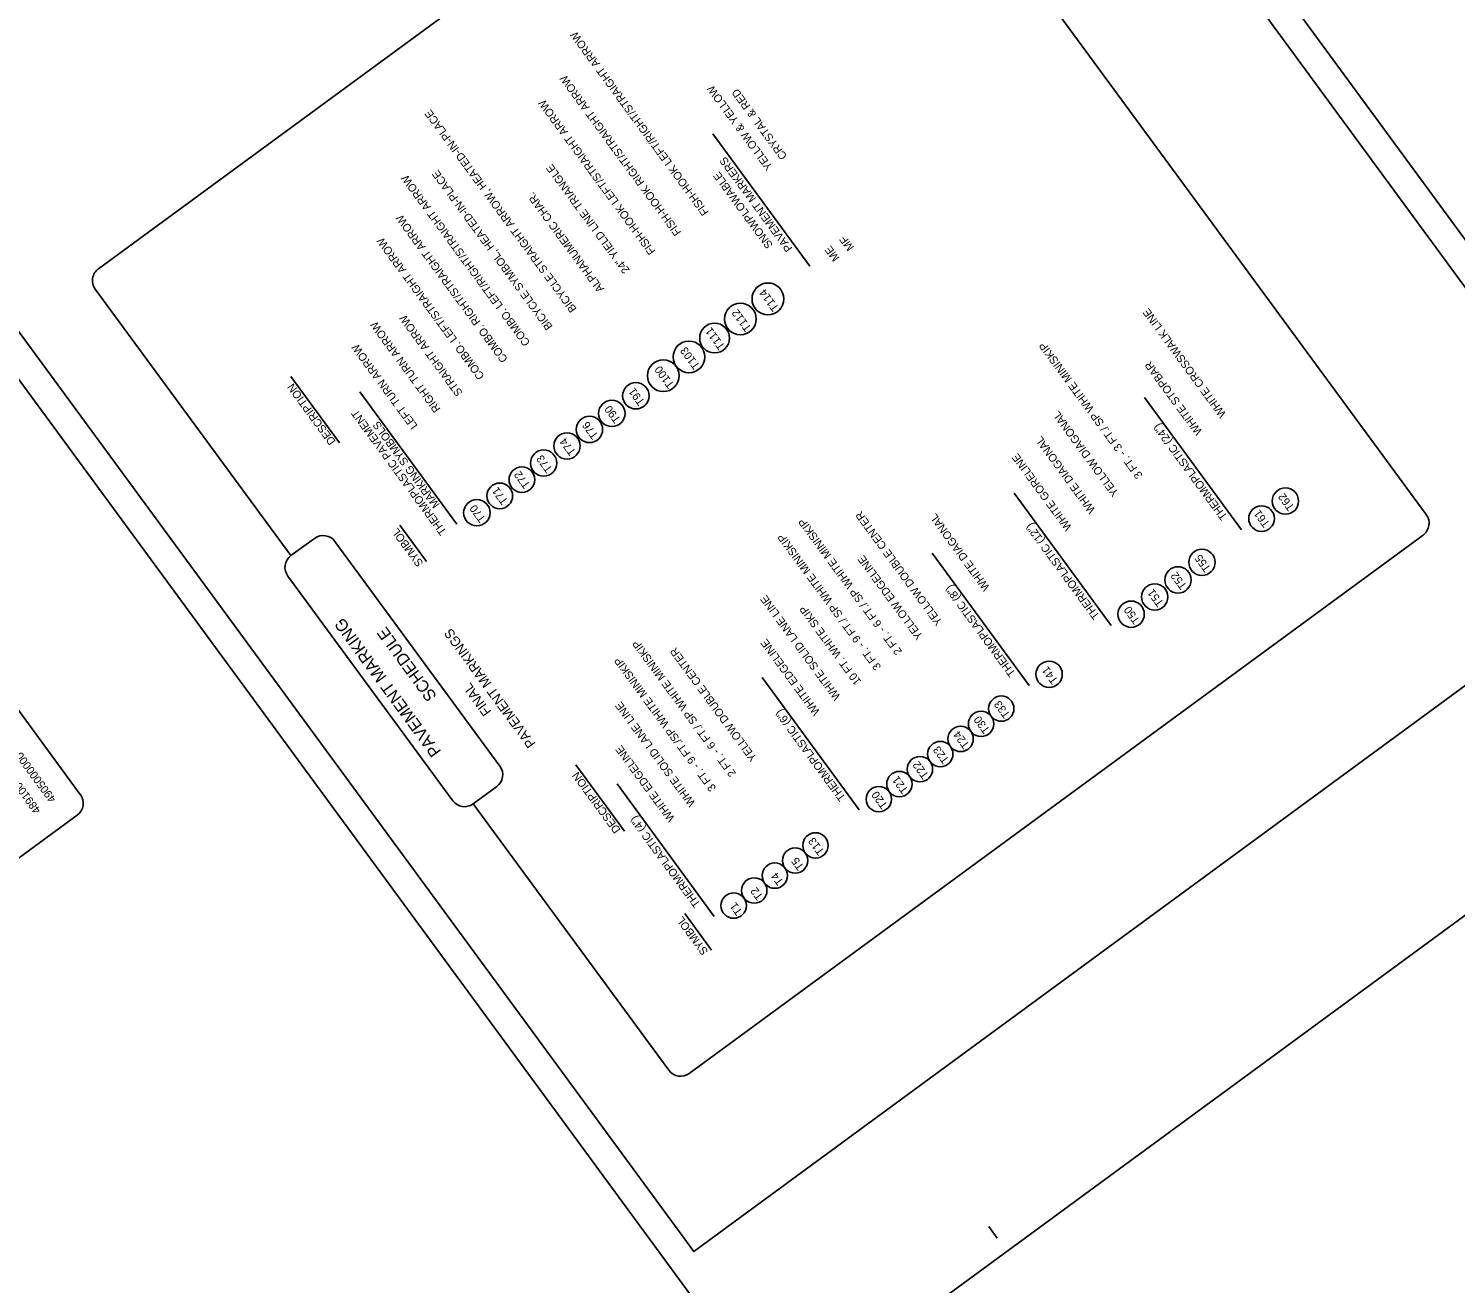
# Model space of a CAD drawing. Extents: x 719153 to 721402, y 581205 to 583188.
# Drawn here: x 720080 to 720834, y 581830 to 582493 of the extents above; entities that cross this region are included whole.
import ezdxf

# ---------------------------------------------------------------- set-up
doc = ezdxf.new("R2010")
doc.units = 0
for name, color, linetype in [('Default', 7, 'Continuous'), ('Old_Level_1', 7, 'Continuous'), ('Old_Level_50', 7, 'Continuous'), ('Sheet Plot Border Inside CELL', 7, 'Continuous'), ('Sheet Sticker Incomplete CELL', 7, 'Continuous')]:
    doc.layers.add(name, color=color, linetype=linetype)

msp = doc.modelspace()

# ---------------------------------------------------------------- linework, layer by layer
at = {"layer": 'Default'}
for p, q in [((719824.66, 582472.96), (720107.28, 582088.04)), ((720037.42, 582027.11), (720105.64, 582077.23))]:
    msp.add_line(p, q, dxfattribs=at)
msp.add_arc((720101.06, 582083.45), 7.73, 306.36664, 36.36664, dxfattribs=at)
at = {"layer": 'Old_Level_1'}
for centre, radius in [((720470.61, 582349.98), 8.4), ((720456.09, 582339.33), 8.37), ((720442.44, 582329.3), 7.88), ((720428.88, 582319.35), 8.37), ((720415.31, 582309.39), 8.39), ((720400.83, 582298.78), 6.97), ((720388.13, 582289.47), 6.97), ((720376.32, 582280.98), 6.96), ((720364.45, 582272.27), 6.96), ((720352.12, 582263.22), 6.96), ((720340.6, 582254.45), 6.78), ((720328.93, 582245.89), 6.78), ((720744.08, 582243.14), 6.96), ((720316.81, 582236.99), 6.97), ((720731.47, 582233.89), 6.78), ((720699.96, 582210.77), 6.96), ((720687.31, 582201.49), 6.96), ((720675.02, 582192.47), 6.96), ((720662.55, 582183.36), 6.96), ((720619.23, 582151.59), 6.96), ((720593.95, 582133.45), 6.7), ((720583.25, 582125.38), 6.7), ((720572.46, 582117.44), 6.7), ((720561.71, 582109.45), 6.7), ((720550.95, 582101.47), 6.7), ((720540.1, 582093.61), 6.7), ((720529.23, 582085.63), 6.7), ((720495.75, 582061.17), 6.7), ((720485, 582053.18), 6.7), ((720474.25, 582045.19), 6.7), ((720463.4, 582037.34), 6.7), ((720452.52, 582029.36), 6.7)]:
    msp.add_circle(centre, radius, dxfattribs=at)
at = {"layer": 'Old_Level_50'}
msp.add_lwpolyline([(721009.35, 582149.27), (720410.24, 582965.86), (719878.1, 582575.44), (720477.21, 581758.85)], close=True, dxfattribs=at)
at = {"layer": 'Sheet Plot Border Inside CELL'}
for p, q in [((720591.8, 581853.7), (720587.36, 581859.75)), ((720431.1, 581847.05), (720431.1, 581847.05))]:
    msp.add_line(p, q, dxfattribs=at)
msp.add_lwpolyline([(719899.07, 582572.22), (720431.46, 581846.57), (720939.41, 582219.25), (720407.02, 582944.89)], close=True, dxfattribs=at)
at = {"layer": 'Sheet Sticker Incomplete CELL'}
for p, q in [((720116.85, 582365.91), (720504.77, 582650.51)), ((720818.48, 582236), (720515.57, 582648.85)), ((720492.79, 582367.32), (720441.52, 582437.29)), ((720218.57, 582214.29), (720115.19, 582355.1)), ((720244.29, 582273.93), (720218.6, 582309)), ((720306.31, 582230.96), (720255.05, 582300.93)), ((720720.95, 582227.89), (720669.69, 582297.86)), ((720651.99, 582177.42), (720600.72, 582247.39)), ((720290.26, 582211.13), (720276.08, 582230.49)), ((720816.84, 582225.16), (720526.73, 582012.31)), ((720218.57, 582214.29), (720231.04, 582223.44)), ((720241.85, 582221.78), (720328.99, 582103.08)), ((720608.67, 582145.64), (720557.41, 582215.61)), ((720216.91, 582203.49), (720304.06, 582084.78)), ((720518.83, 582079.96), (720467.57, 582149.93)), ((720394.85, 582068.69), (720369.17, 582103.75)), ((720314.87, 582083.12), (720327.33, 582092.27)), ((720442.13, 582023.68), (720390.87, 582093.65)), ((720418.26, 581942.31), (720314.87, 582083.13)), ((720440.82, 582005.89), (720426.64, 582025.24)), ((720429.07, 581940.65), (720526.73, 582012.31))]:
    msp.add_line(p, q, dxfattribs=at)
for centre, start, end in [((720121.42, 582359.67), 126.26669, 216.26669), ((720812.27, 582231.39), 306.26669, 36.26669), ((720235.62, 582217.21), 36.26669, 126.26669), ((720223.15, 582208.06), 126.26669, 216.26669), ((720322.76, 582098.5), 306.26664, 36.26664), ((720310.29, 582089.36), 216.26664, 306.26664), ((720424.49, 581946.89), 216.26664, 306.26664)]:
    msp.add_arc(centre, 7.73, start, end, dxfattribs=at)

# ---------------------------------------------------------------- texts
at = {"layer": 'Old_Level_1'}
for s, height, rotation, p in [('FISH-HOOK LEFT/RIGHT/STRAIGHT ARROW', 4.21, 126.22647, (720439.55, 582395.87)), ('FISH-HOOK RIGHT/STRAIGHT ARROW', 4.21, 126.22647, (720424.98, 582385.18)), ('YELLOW & YELLOW', 4.21, 126.22647, (720473.34, 582419.85)), ('CRYSTAL & RED', 4.21, 126.22647, (720480.97, 582425.45)), ('FISH-HOOK LEFT/STRAIGHT ARROW', 4.21, 126.22647, (720411.4, 582375.22)), ('BICYCLE STRAIGHT ARROW, HEATED-IN-PLACE', 4.21, 126.22647, (720369.75, 582344.72)), ('24" YIELD LINE TRIANGLE', 4.21, 126.22647, (720397.82, 582365.27)), ('PAVEMENT MARKERS', 4.21, 126.22647, (720483.84, 582376.76)), ('COMBO. LEFT/RIGHT/STRAIGHT ARROW', 4.21, 126.22647, (720345.23, 582326.92)), ('BICYCLE SYMBOL, HEATED-IN-PLACE', 4.21, 126.22647, (720357.05, 582335.4)), ('SNOWPLOWABLE', 4.21, 126.22647, (720473.46, 582378.47)), ('ALPHANUMERIC CHAR.', 4.21, 126.22647, (720384.23, 582355.31)), ('COMBO. RIGHT/STRAIGHT ARROW', 4.21, 126.22647, (720333.36, 582318.21)), ('COMBO. LEFT/STRAIGHT ARROW', 4.21, 126.22647, (720321.03, 582309.17)), ('ME', 4.21, 126.22647, (720508.69, 582371.67)), ('MF', 4.21, 126.22647, (720516.32, 582377.27)), ('T114', 4.21, 126.26667, (720476.68, 582345.26)), ('WHITE CROSSWALK LINE', 4.21, 126.22647, (720712.96, 582289.13)), ('RIGHT TURN ARROW', 4.21, 126.22647, (720297.84, 582291.84)), ('STRAIGHT ARROW', 4.21, 126.22647, (720309.51, 582300.4)), ('T112', 4.21, 126.26667, (720462.15, 582334.64)), ('T111', 4.21, 126.26667, (720448.2, 582325.01)), ('LEFT TURN ARROW', 4.21, 126.22647, (720285.71, 582282.95)), ('T103', 4.21, 126.26667, (720434.94, 582314.66)), ('3 FT. - 3 FT./ SP WHITE MINISKIP', 4.21, 126.22647, (720668.83, 582256.79)), ('WHITE STOPBAR', 4.21, 126.22647, (720700.35, 582279.89)), ('T100', 4.21, 126.26667, (720421.37, 582304.68)), ('DESCRIPTION', 4.21, 126.22647, (720242.44, 582274.7)), ('T91', 4.21, 126.26667, (720405.78, 582295.6)), ('T90', 4.21, 126.26667, (720393.08, 582286.28)), ('THERMOPLASTIC PAVEMENT', 4.21, 126.22647, (720301.01, 582227.07)), ('MARKING SYMBOLS', 4.21, 126.22647, (720297.41, 582241.32)), ('T76', 4.21, 126.26667, (720381.25, 582277.81)), ('YELLOW DIAGONAL', 4.21, 126.22647, (720656.17, 582247.51)), ('WHITE DIAGONAL', 4.21, 126.22647, (720643.88, 582238.49)), ('THERMOPLASTIC (24")', 4.21, 126.22647, (720713.6, 582235.02)), ('T74', 4.21, 126.26667, (720369.38, 582269.1)), ('T73', 4.21, 126.26667, (720357.05, 582260.06)), ('WHITE GORELINE', 4.21, 126.22647, (720631.41, 582229.38)), ('T72', 4.21, 126.26667, (720345.24, 582251.69)), ('T71', 4.21, 126.26667, (720333.57, 582243.13)), ('T62', 4.21, 126.26667, (720749.01, 582239.98)), ('T70', 4.21, 126.26667, (720321.76, 582233.81)), ('2 FT. - 6 FT./ SP WHITE MINISKIP', 4.21, 126.22647, (720541.7, 582163.69)), ('YELLOW DOUBLE CENTER', 4.21, 126.22647, (720562.99, 582179.32)), ('WHITE DIAGONAL', 4.21, 126.22647, (720588.09, 582197.6)), ('T61', 4.21, 126.26667, (720736.11, 582231.13)), ('SYMBOL ', 4.21, 126.22647, (720288.74, 582210.39)), ('3 FT. - 9 FT./ SP WHITE MINISKIP', 4.21, 126.22647, (720530.68, 582155.56)), ('THERMOPLASTIC (12")', 4.21, 126.22647, (720646.17, 582182.46)), ('YELLOW EDGELINE', 4.21, 126.22647, (720552.74, 582171.8)), ('T55', 4.21, 126.26667, (720704.9, 582207.6)), ('T52', 4.21, 126.26667, (720692.25, 582198.32)), ('THERMOPLASTIC (8")', 4.21, 126.22647, (720601.73, 582152.21)), ('T51', 4.21, 126.26667, (720679.95, 582189.3)), ('WHITE SOLID LANE LINE ', 4.21, 126.22647, (720509.23, 582139.83)), ('10 FT. WHITE SKIP', 4.21, 126.22647, (720520.14, 582147.83)), ('T50', 4.21, 126.26667, (720667.49, 582180.18)), ('PAVEMENT MARKINGS', 5.1121, 126.22647, (720348.14, 582115.02)), ('2 FT. - 6 FT./ SP WHITE MINISKIP', 4.21, 126.22647, (720453.97, 582099.28)), ('YELLOW DOUBLE CENTER', 4.21, 126.22647, (720464.99, 582107.42)), ('WHITE EDGELINE ', 4.21, 126.22647, (720498.32, 582131.83)), ('3 FT. - 9 FT./SP WHITE MINISKIP', 4.21, 126.22647, (720443.44, 582091.55)), ('T41', 4.21, 126.26667, (720624.18, 582148.4)), ('FINAL', 5.112, 126.22647, (720324.7, 582131.88)), ('WHITE SOLID LANE LINE ', 4.21, 126.22647, (720432.53, 582083.55)), ('T33', 4.21, 126.26667, (720598.88, 582130.29)), ('THERMOPLASTIC (6")', 4.21, 126.22647, (720511.93, 582086.48)), ('T30', 4.21, 126.26667, (720588.19, 582122.21)), ('T24', 4.21, 126.26667, (720577.39, 582114.28)), ('4905000000-N', 4.21, 126.22647, (720094.67, 582085.69)), ('WHITE EDGELINE ', 4.21, 126.22647, (720421.62, 582075.55)), ('T23', 4.21, 126.26667, (720566.64, 582106.29)), ('4891000000-E', 4.21, 126.22647, (720086.61, 582079.78)), ('T22', 4.21, 126.26667, (720555.89, 582098.3)), ('DESCRIPTION', 4.21, 126.22647, (720393, 582069.46)), ('T21', 4.21, 126.26667, (720545.04, 582090.45)), ('T20', 4.21, 126.26667, (720534.16, 582082.47)), ('THERMOPLASTIC (4")', 4.21, 126.22647, (720435.23, 582030.2)), ('T13', 4.21, 126.26667, (720500.69, 582058)), ('T5', 4.21, 126.26667, (720489.94, 582050.01)), ('T4', 4.21, 126.26667, (720479.18, 582042.02)), ('T2', 4.21, 126.26667, (720468.33, 582034.17)), ('T1', 4.21, 126.26667, (720457.45, 582026.19)), ('SYMBOL ', 4.21, 126.22647, (720439.3, 582005.15))]:
    msp.add_text(s, height=height, rotation=rotation, dxfattribs=at).set_placement(p)
at = {"layer": 'Sheet Sticker Incomplete CELL'}
for s, p in [('PAVEMENT MARKING', (720298.21, 582110.83)), ('SCHEDULE', (720295.89, 582140.13))]:
    msp.add_text(s, height=6.315, rotation=126.22647, dxfattribs=at).set_placement(p)

doc.saveas('drawing.dxf')
